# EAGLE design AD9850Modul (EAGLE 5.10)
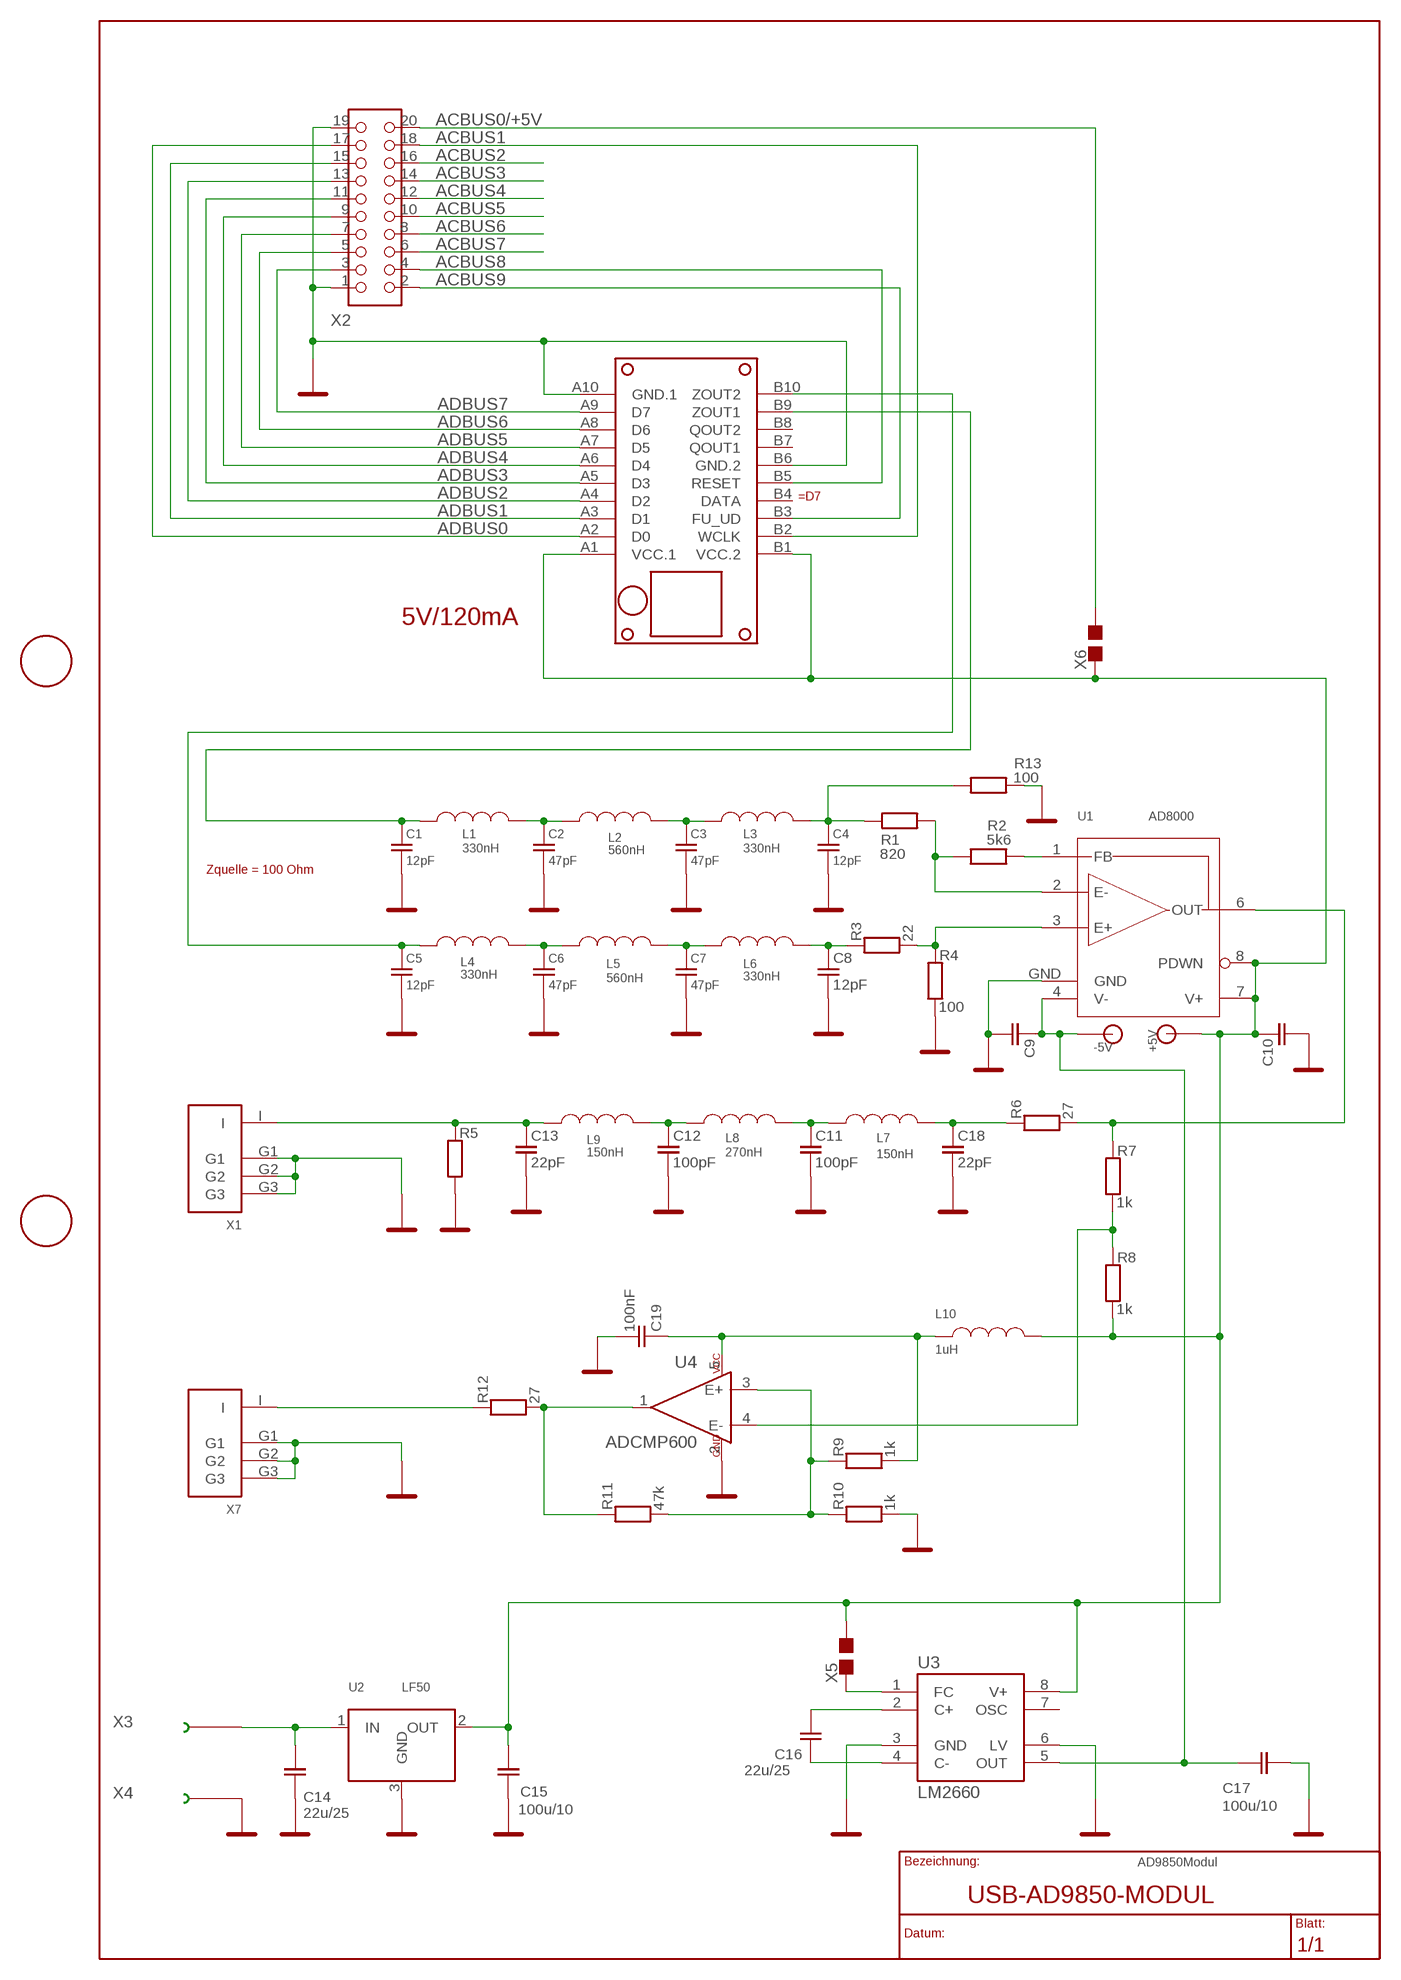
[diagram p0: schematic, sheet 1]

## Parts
C1  12pF  SMD-0603  [SOT-0603]
C2  47pF  SMD-0603  [SOT-0603]
C3  47pF  SMD-0603  [SOT-0603]
C4  12pF  SMD-0603  [SOT-0603]
C5  12pF  SMD-0603  [SOT-0603]
C6  47pF  SMD-0603  [SOT-0603]
C7  47pF  SMD-0603  [SOT-0603]
C8  12pF  SMD-0603  [SOT-0603]
C9  SMD-0603  [SOT-0603]
C10  SMD-0603  [SOT-0603]
C11  100pF  SMD-0603  [SOT-0603]
C12  100pF  SMD-0603  [SOT-0603]
C13  22pF  SMD-0603  [SOT-0603]
C14  22u/25  SMD-1210  [SOT-1210]
C15  100u/10  SMD-1210  [SOT-1210]
C16  22u/25  SMD-1210  [SOT-1210]
C17  100u/10  SMD-1210  [SOT-1210]
C18  22pF  SMD-0603  [SOT-0603]
C19  100nF  SMD-0603  [SOT-0603]
L1  330nH  SMD-1008  [SMD-1008]
L2  560nH  SMD-1008  [SMD-1008]
L3  330nH  SMD-1008  [SMD-1008]
L4  330nH  SMD-1008  [SMD-1008]
L5  560nH  SMD-1008  [SMD-1008]
L6  330nH  SMD-1008  [SMD-1008]
L7  150nH  SMD-1008  [SMD-1008]
L8  270nH  SMD-1008  [SMD-1008]
L9  150nH  SMD-1008  [SMD-1008]
L10  1uH  SMD-1008  [SMD-1008]
M1  CHINA_DDS  [CHINA_DDS]
R1  820  SMD-0603  [SMD-0603]
R2  5k6  SMD-0603  [SMD-0603]
R3  22  SMD-0603  [SMD-0603]
R4  100  SMD-0603  [SMD-0603]
R5  SMD-0603  [SMD-0603]
R6  27  SMD-0603  [SMD-0603]
R7  1k  SMD-0603  [SMD-0603]
R8  1k  SMD-0603  [SMD-0603]
R9  1k  SMD-0603  [SMD-0603]
R10  1k  SMD-0603  [SMD-0603]
R11  47k  SMD-0603  [SMD-0603]
R12  27  SMD-0603  [SMD-0603]
R13  100  SMD-0603  [SMD-0603]
U1  AD8000  [SO-8EXP]
U2  LF50  LF-XXX  [DPAK]
U3  LM2660  [SO-8]
U4  ADCMP600  [SOT23-5]
X1  CINCH-S  [CINCH-S]
X2  BUCHSE2X10/90  [BUCHSE2X10/90]
X3  LÖTÖSEQ  [LÖTÖSEQ]
X4  LÖTÖSEQ  [LÖTÖSEQ]
X5  PATCH  [PATCH]
X6  PATCH  [PATCH]
X7  CINCH-S  [CINCH-S]

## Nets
+5V: C10.2 C15.2 L10.2 M1.A1(VCC.1) M1.B1(VCC.2) R8.1 U1.7(V+) U1.8(PDWN) U2.2(OUT) U3.8(V+) X5.2 X6.1
-5V: C9.2 C17.2 U1.4(V-) U3.5(OUT)
ACBUS0/+5V: X2.20 X6.2
ACBUS1: M1.B2(WCLK) X2.18
ACBUS2: X2.16
ACBUS3: X2.14
ACBUS4: X2.12
ACBUS5: X2.10
ACBUS6: X2.8
ACBUS7: X2.6
ACBUS8: M1.B5(RESET) X2.4
ACBUS9: M1.B3(FU_UD) X2.2
ADBUS0: M1.A2(D0) X2.17
ADBUS1: M1.A3(D1) X2.15
ADBUS2: M1.A4(D2) X2.13
ADBUS3: M1.A5(D3) X2.11
ADBUS4: M1.A6(D4) X2.9
ADBUS5: M1.A7(D5) X2.7
ADBUS6: M1.A8(D6) X2.5
ADBUS7: M1.A9(D7) X2.3
GND: C1.1 C2.1 C3.1 C4.1 C5.1 C6.1 C7.1 C8.1 C9.1 C10.1 C11.1 C12.1 C13.1 C14.1 C15.1 C17.1 C18.1 C19.1 M1.A10(GND.1) M1.B6(GND.2) R4.1 R5.1 R10.1 R13.1 U1.GND U2.3(GND) U3.3(GND) U3.6(LV) U4.2(GND) X1.G1 X1.G2 X1.G3 X2.1 X2.19 X4.1 X7.G1 X7.G2 X7.G3
N$1: R2.1 U1.1(FB)
N$2: R1.1 R2.2 U1.2(E-)
N$3: C1.2 L1.1 M1.B9(ZOUT1)
N$4: C2.2 L1.2 L2.1
N$5: C3.2 L2.2 L3.1
N$6: C4.2 L3.2 R1.2 R13.2
N$7: C5.2 L4.1 M1.B10(ZOUT2)
N$8: C6.2 L4.2 L5.1
N$9: C7.2 L5.2 L6.1
N$10: C8.2 L6.2 R3.2
N$11: R3.1 R4.2 U1.3(E+)
N$12: R6.1 R7.2 U1.6(OUT)
N$13: C11.2 L7.1 L8.2
N$14: C12.2 L8.1 L9.2
N$15: C13.2 L9.1 R5.2 X1.I
N$16: C14.2 U2.1(IN) X3.1
N$17: C16.1 U3.4(C-)
N$18: C16.2 U3.2(C+)
N$19: U3.1(FC) X5.1
N$20: C18.2 L7.2 R6.2
N$21: C19.2 L10.1 R9.1 U4.5(VCC)
N$22: R7.1 R8.2 U4.4(E-)
N$23: R9.2 R10.2 R11.1 U4.3(E+)
N$24: R11.2 R12.1 U4.1(OUT)
N$25: R12.2 X7.I
Unconnected: M1.B4(DATA) M1.B7(QOUT1) M1.B8(QOUT2) U3.7(OSC)

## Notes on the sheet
- =D7
- 5V/120mA
- Zquelle = 100 Ohm
- USB-AD9850-MODUL

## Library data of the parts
C1-C13 C18 C19 = C_KERAM:SMD-0603
C14-C17 = C_KERAM:SMD-1210
L1-L10 = L:SMD-1008
M1 = HAMRAD:CHINA_DDS
R1-R13 = R:SMD-0603
U1 = ANALOG_D:AD8000
U2 = SGS:LF-XXX
U3 = NSC:LM2660
U4 = ANALOG_D:ADCMP600: Komparator 3.5 ns
X1 X7 = HAMRAD:CINCH-S
X2 = PINHD-Q:BUCHSE2X10/90
X3 X4 = Z_CONNEC:LÖTÖSEQ
X5 X6 = Z_CONNEC:PATCH

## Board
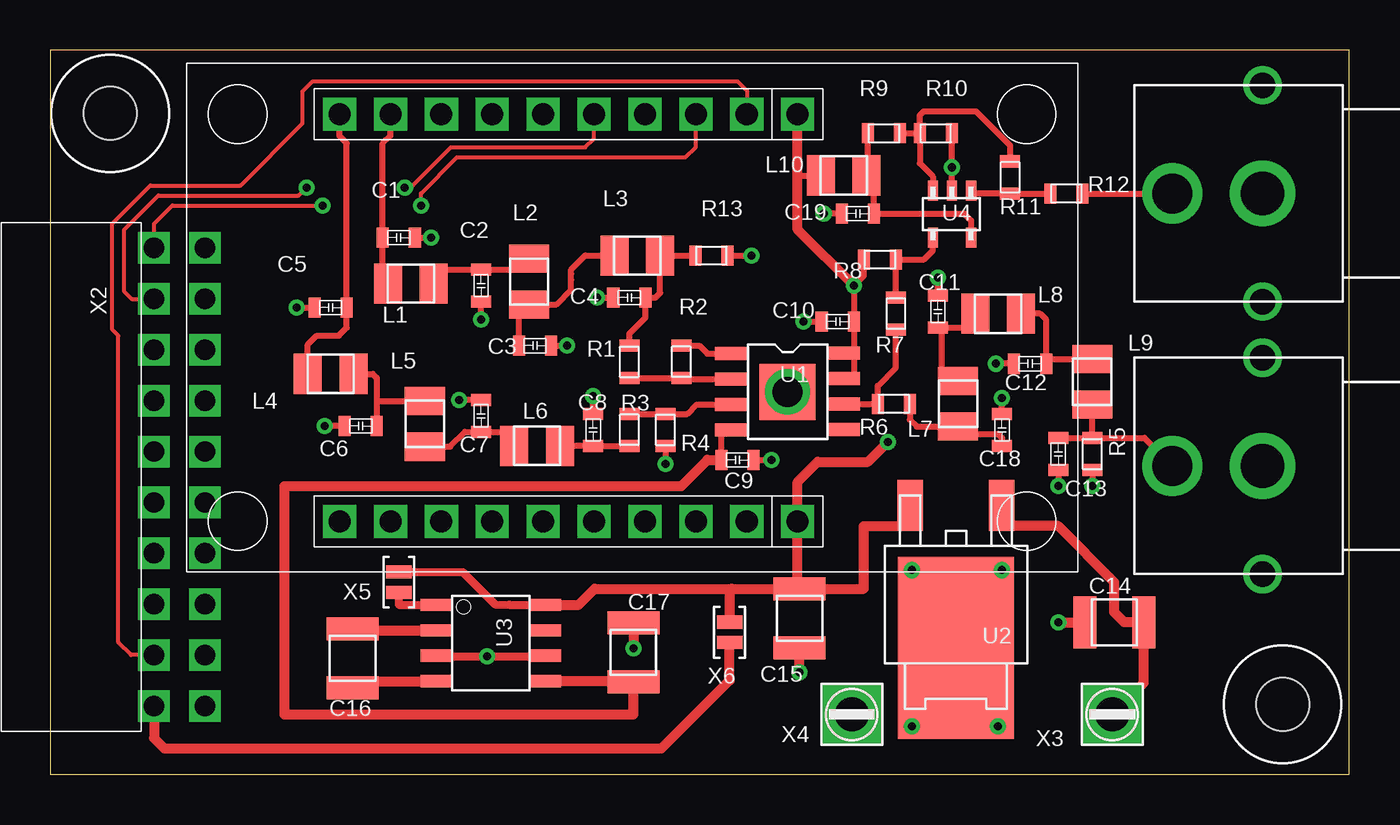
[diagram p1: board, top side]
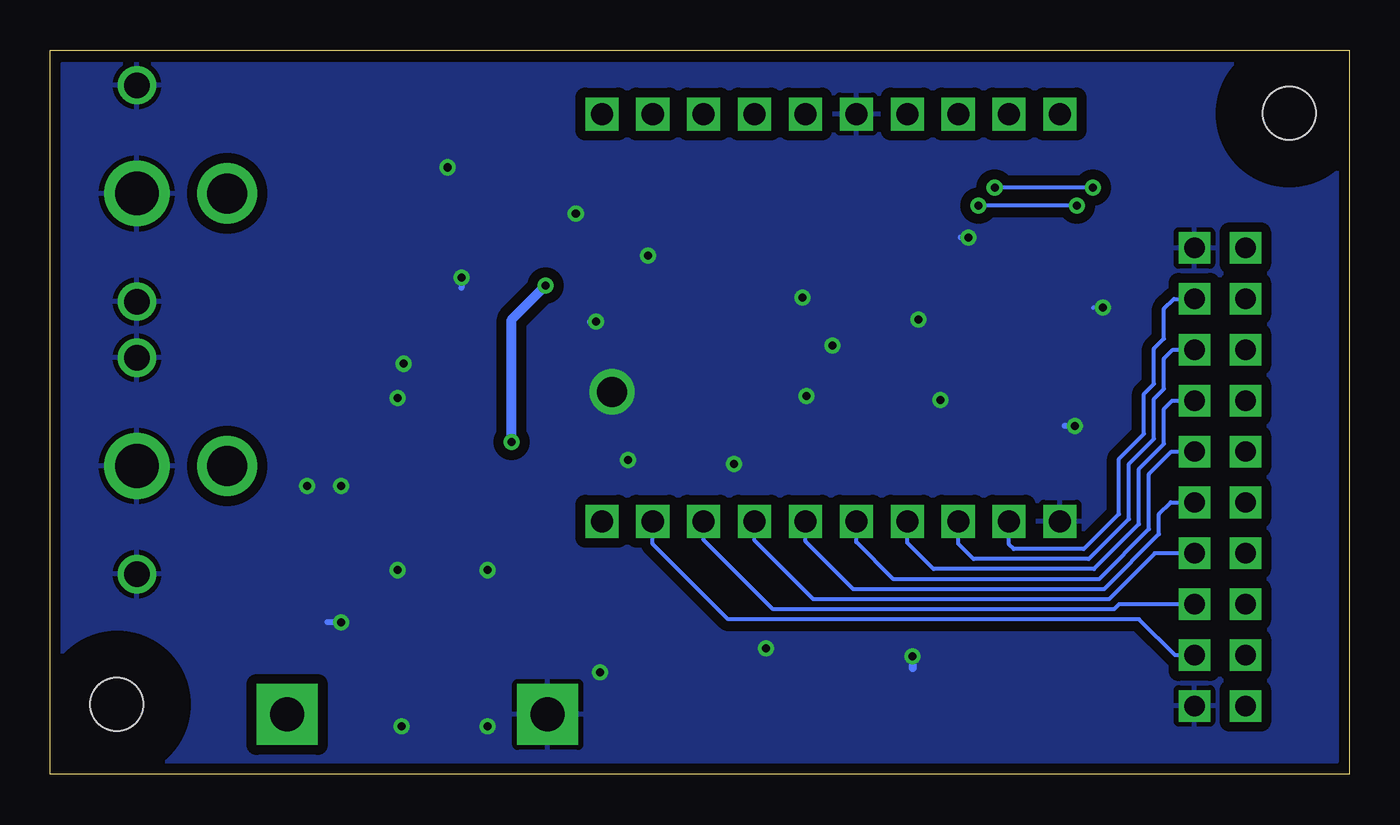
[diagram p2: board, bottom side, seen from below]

Size 64.83 x 36.16 mm. Coordinates in mm from the lower left corner, seen from the top.
Outline: 0,0 64.83,0 64.83,36.16 0,36.16 0,0
Copper layers (1*16): Top 0.035mm / dielectric 1.5mm / Bottom 0.035mm
Design rules "default": minimum track width 0.15mm, minimum drill 0.3mm, track to track 0.15mm, track to pad 0.15mm, pad to pad 0.15mm, via to via 0.15mm, smd to smd 0mil, copper to edge 0.15mm, drill to drill 0.15mm, minimum pad ring 0.15mm, minimum via ring 0.15mm, stop-mask expansion 4mil, vias tented up to drill 0mil, thermal gap 10mil

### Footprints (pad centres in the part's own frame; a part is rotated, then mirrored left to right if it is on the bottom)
SOT-0603 = smd 0.6 x 1: 1 -0.8,0; 2 0.8,0
SOT-1210 = smd 1.143 x 2.591: 1 -1.473,0; 2 1.473,0
SMD-1008 = smd 1.4 x 2: 1 -1.14,0; 2 1.14,0
CHINA_DDS = drill 1.1 square: A1 -10.16,-12.7; A2 -10.16,-10.16; A3 -10.16,-7.62; A4 -10.16,-5.08; A5 -10.16,-2.54; A6 -10.16,0; A7 -10.16,2.54; A8 -10.16,5.08; A9 -10.16,7.62; A10 -10.16,10.16; B1 10.16,-12.7; B2 10.16,-10.16; B3 10.16,-7.62; B4 10.16,-5.08; B5 10.16,-2.54; B6 10.16,0; B7 10.16,2.54; B8 10.16,5.08; B9 10.16,7.62; B10 10.16,10.16
SMD-0603 = smd 0.6 x 1: 1 -0.8,0; 2 0.8,0
SO-8EXP = smd 0.66 x 1.6: 1 -1.905,-2.819; 2 -0.635,-2.819; 3 0.635,-2.819; 4 1.905,-2.819; 5 1.88,2.819; 6 0.61,2.819; 7 -0.66,2.819; 8 -1.93,2.819 | smd 2.794 x 2.794: GND 0,0
DPAK = smd 1.27 x 2.54: 1 -2.286,-2.032; 2 2.286,-2.032 | smd 5.8 x 9.1: 3 0,5.08
SO-8 = smd 0.61 x 1.524: 1 -1.27,-2.743; 2 0,-2.743; 3 1.27,-2.743; 4 2.54,-2.743; 5 2.54,2.743; 6 1.27,2.743; 7 0,2.743; 8 -1.27,2.743
SOT23-5 = smd 0.508 x 1.016: 1 -0.953,-1.143; 2 0,-1.143; 3 0.953,-1.143; 4 0.953,1.206; 5 -0.953,1.206
DRIL-2,5 = hole 2.642: 0,0
CINCH-S = drill 2.184 pad 2.8 round: G1 0,0 | drill 1.27 pad 1.778 round: G2 0,5.4; G3 0,-5.4 | drill 2 pad 2.54 round: I 4.5,0
BUCHSE2X10/90 = drill 1.016 pad 1.575 square: 1 -11.43,-1.27; 2 -11.43,-3.81; 3 -8.89,-1.27; 4 -8.89,-3.81; 5 -6.35,-1.27; 6 -6.35,-3.81; 7 -3.81,-1.27; 8 -3.81,-3.81; 9 -1.27,-1.27; 10 -1.27,-3.81; 11 1.27,-1.27; 12 1.27,-3.81; 13 3.81,-1.27; 14 3.81,-3.81; 15 6.35,-1.27; 16 6.35,-3.81; 17 8.89,-1.27; 18 8.89,-3.81; 19 11.43,-1.27; 20 11.43,-3.81
LÖTÖSEQ = drill 1.702 pad 3.048 square: 1 0,0
PATCH = smd 0.66 x 1.27: 1 -0.508,0; 2 0.508,0

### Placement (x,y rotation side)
C1  17.4,26.8 180 top
C2  21.5,24.4 90 top
C3  24.2,21.4 180 top
C4  28.9,23.8 0 top
C5  14,23.3 0 top
C6  15.5,17.4 0 top
C7  21.5,17.9 270 top
C8  27.1,17.2 270 top
C9  34.3,15.7 180 top
C10  39.3,22.6 0 top
C11  44.3,23.1 270 top
C12  48.9,20.5 0 top
C13  50.3,16 90 top
C14  53.1,7.6 0 top
C15  37.4,7.8 90 top
C16  15.1,5.8 90 top
C17  29.1,6.1 270 top
C18  47.5,17.2 270 top
C19  40.3,28 0 top
L1  18,24.5 0 top
L2  23.9,24.6 270 top
L3  29.3,25.9 0 top
L4  14,20 0 top
L5  18.7,17.5 270 top
L6  24.3,16.4 0 top
L7  45.3,18.5 270 top
L8  47.3,23 180 top
L9  52,19.6 90 top
L10  39.6,29.9 180 top
M1  24.6,22.8 90 top
R1  28.9,20.6 90 top
R2  31.5,20.6 270 top
R3  28.9,17.2 270 top
R4  30.7,17.2 90 top
R5  52,16 90 top
R6  42.1,18.5 0 top
R7  42.2,23 270 top
R8  41.4,25.7 0 top
R9  41.6,32 0 top
R10  44.2,32 180 top
R11  47.9,29.8 270 top
R12  50.7,29 0 top
R13  33,25.9 180 top
U1  36.8,19.1 270 top
U2  45.2,11.4 180 top
U3  22,7.2 270 top
U4  45,28 180 top
U$34  [DRIL-2,5]  3,33 0 top
U$35  [DRIL-2,5]  61.5,3.5 0 top
X1  60.5,15.4 180 top
X2  9,14.85 270 top
X3  53,3 90 top
X4  40,3 90 top
X5  17.4,9.6 90 top
X6  33.9,7.1 270 top
X7  60.5,29 180 top

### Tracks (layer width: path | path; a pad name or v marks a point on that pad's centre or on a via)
+5V  (via drill 0.4 pad 0.8)
  Top 0.3: U1.7 40.1,19.76 40.1,21.03 | 40.1,21.03 U1.8 | 40.1,21.03 C10.2 v40.1,24.4 40.6,24.9 R8.1 | C15.2 37.3,9.27 | 37.3,29.9 L10.2
  Top 0.4: U3.8 22.91,8.47 22.2,8.5 20.59,10.11 X5.2
  Top 0.5: v41.8,16.6 40.8,15.6 38.3,15.6 37.3,14.6 M1.A1 37.3,9.27 | M1.B1 37.3,29.9 37.3,27.2 v40.1,24.4 | U2.2 42.91,12.4 40.6,12.4 40.6,9.27 C15.2 34,9.27 | U3.8 26.37,8.47 27.17,9.27 34,9.27 | X6.1 33.9,9.17 34,9.27
  Bottom 0.5: v41.8,16.6 41.8,22.7 v40.1,24.4
-5V
  Top 0.3: U1.4 33.5,17.2 C9.2
  Top 0.4: C17.2 29.1,4.66
  Top 0.5: C9.2 32.8,15.7 31.5,14.4 11.7,14.4 11.7,3 29.1,3 C17.2 | 29.1,4.66 U3.5
ACBUS0/+5V
  Top 0.5: X2.20 5.19,1.81 5.7,1.3 30.5,1.3 33.9,4.7 X6.2
ACBUS1
  Top 0.2: X2.18 4.04,5.96 3.4,6.6 3.4,21.9 3.1,22.2 3.1,27.5 5,29.4 9.5,29.4 12.6,32.5 12.6,34.1 13.1,34.6 34.3,34.6 34.76,34.14 M1.B2
ACBUS8  (via drill 0.4 pad 0.8)
  Top 0.2: X2.4 4.06,23.74 3.7,24.1 3.7,27.2 5.4,28.9 12.4,28.9 v12.8,29.3 | M1.B5 27.14,31.74 26.7,31.3 20,31.3 18,29.3 v17.7,29.3
  Bottom 0.2: v12.8,29.3 v17.7,29.3
ACBUS9  (via drill 0.4 pad 0.8)
  Top 0.2: X2.2 5.19,27.49 6.1,28.4 v13.6,28.4 | M1.B3 32.22,31.32 31.7,30.8 20.3,30.8 18.5,29 v18.5,28.4
  Bottom 0.2: v13.6,28.4 v18.5,28.4
ADBUS0
  Bottom 0.2: M1.A2 34.76,11.51 31,7.75 10.5,7.75 8.71,5.96 X2.17
ADBUS1
  Bottom 0.2: M1.A3 32.22,11.72 28.75,8.25 11.75,8.25 11.5,8.5 X2.15
ADBUS2
  Bottom 0.2: M1.A4 29.68,11.68 26.75,8.75 12,8.75 9.71,11.04 X2.13
ADBUS3
  Bottom 0.2: M1.A5 27.14,11.64 24.75,9.25 12.25,9.25 9.5,12 9.5,13 8.92,13.58 X2.11
ADBUS4
  Bottom 0.2: M1.A6 24.6,11.6 22.75,9.75 12.5,9.75 10,12.25 10,15 8.88,16.12 X2.9
ADBUS5
  Bottom 0.2: M1.A7 22.06,11.56 20.75,10.25 12.75,10.25 10.5,12.5 10.5,15.25 9.25,16.5 9.25,18.25 8.84,18.66 X2.7
ADBUS6
  Bottom 0.2: M1.A8 19.52,11.52 18.75,10.75 13,10.75 11,12.75 11,15.5 9.75,16.75 9.75,18.75 9.25,19.25 9.25,20.75 8.8,21.2 X2.5
ADBUS7
  Bottom 0.2: M1.A9 16.98,11.48 16.75,11.25 13.25,11.25 11.5,13 11.5,15.75 10.25,17 10.25,19 9.75,19.5 9.75,21.25 9.25,21.75 9.25,23.25 8.76,23.74 X2.3
GND  (via drill 0.4 pad 0.8, 1.5 pad 0.8)
  Top 0.3: v12.3,23.3 C5.1 | C1.1 v19,26.8 | C6.1 v13.7,17.4 | v21.5,22.7 C2.1 | C3.1 v25.8,21.4 | C8.1 v27.1,18.9 | C7.1 v20.4,18.7 | R4.1 v30.7,15.5 | C9.1 v36,15.7 | v37.6,22.6 C10.1 | U2.3 45.2,4.5 v47.3,2.4 | v27.3,23.8 C4.1 | R5.1 v52,14.4 | C13.1 v50.3,14.4 | C12.1 v47.2,20.5 | C11.1 v44.3,24.8 | C18.1 v47.5,18.8 | C19.1 v38.6,28 | U4.2 v45,30.3 R10.1 | R13.1 v35,25.9
  Top 0.4: U3.3 19.29,5.9 v21.8,5.9 24.71,5.9 U3.6 | C17.1 29.1,7.6
  Top 0.5: v37.4,5.1 C15.1 | v50.3,7.6 C14.1 | 29.1,7.6 v29.1,6.3
  Bottom 0.2: v12.3,23.3 12.8,23.3
  Bottom 0.3: v19,26.8 19.4,26.8 | v13.7,17.4 14.2,17.4 | v21.5,22.7 21.5,22.5 | v25.8,21.4 25.7,21.4 | v27.1,18.9 27.1,18.7 | v20.4,18.7 20.6,18.7 | v30.7,15.5 30.7,15.6 30.6,15.7 | v36,15.7 35.8,15.7 | v37.6,22.6 37.9,22.6 | v37.4,5.1 37.4,5.3 | v50.3,7.6 51,7.6 | v27.3,23.8 27.4,23.8 | v52,14.4 52,14.5 | v50.3,14.4 50.3,14.5 | v47.2,20.5 47.4,20.5 | v44.3,24.8 44.3,24.3 | v47.5,18.8 47.5,18.6 | v38.6,28 38.8,28 | v45,30.3 45,30.2 | v35,25.9 34.9,25.9
  Bottom 0.4: v21.8,5.9 21.8,5.3
  other vias: 36.8,19.1 47.5,10.2 43,10.2 43,2.4
  pour Bottom (isolate 0.5): 0.64,0.64 64.22,0.64 64.22,35.47 0.64,35.47
N$1
  Top 0.3: U1.1 32.8,21 32.4,21.4 R2.1
N$2
  Top 0.3: R1.1 R2.2 31.57,19.73 U1.2
N$3
  Top 0.3: M1.B9 16.98,31.88 16.6,31.5 C1.2 16.6,24.5 L1.1
N$4
  Top 0.3: L1.2 19.14,25.2 C2.2 23.9,25.2 L2.1
N$5
  Top 0.3: L3.1 26.7,25.9 26,25.2 26,25 26,24.7 26,24.2 25.26,23.46 L2.2 23.4,22.96 C3.2
N$6
  Top 0.3: R1.2 28.9,22 29.7,22.8 C4.2 30.2,23.8 30.44,24.04 L3.2 R13.2
N$7
  Top 0.3: M1.B10 14.44,31.86 14.8,31.5 C5.2 14.8,22.3 14.4,21.9 13.3,21.9 12.86,21.46 L4.1
N$8
  Top 0.3: L4.2 16.1,20 16.3,19.8 16.3,18.6 | 16.3,18.6 C6.2 | L5.1 16.34,18.64 16.3,18.6
N$9
  Top 0.3: L5.2 19.96,16.36 20.7,17.1 C7.2 23.16,17.1 L6.1
N$10
  Top 0.3: R3.2 C8.2 L6.2
N$11
  Top 0.3: R3.1 R4.2 31.8,18 32.27,18.46 U1.3
N$12
  Top 0.3: U1.6 R6.1 41.3,19.4 42.2,20.3 R7.2
N$13
  Top 0.3: L7.1 44.5,19.64 44.5,22.3 C11.2 46.16,22.3 L8.2
N$14
  Top 0.3: L8.1 49.4,23 49.7,22.7 C12.2 49.94,20.74 L9.2
N$15
  Top 0.3: X1.I 54.6,16.8 R5.2 | C13.2 R5.2 | R5.2 L9.1
N$16
  Top 0.5: U2.1 47.49,12.4 50.3,12.4 53.1,9.6 53.1,8.1 53.6,7.6 C14.2 54.57,4.57 X3.1
N$17
  Top 0.5: U3.4 15.1,4.66 C16.1
N$18
  Top 0.4: C16.2 15.1,7.2
  Top 0.5: 15.1,7.2 U3.2
N$19
  Top 0.4: U3.1 17.39,8.47 X5.1
N$20
  Top 0.3: R6.2 42.9,17.7 43.24,17.36 L7.2 45.66,17 47.3,17 47.5,16.8 C18.2
N$21
  Top 0.3: U4.5 45.95,27.65 45.6,28 C19.2 41.1,29.54 arc90 L10.1 40.8,29.96 R9.1
N$22
  Top 0.3: R7.1 R8.2 43.6,25.7 44.05,26.15 U4.4
N$23
  Top 0.3: U4.3 44.05,29.85 43.4,30.5 R10.2 | R9.2 R10.2 | R11.1 47.9,31.4 46.2,33.1 43.6,33.1 43.4,32.9 R10.2
N$24
  Top 0.3: R12.1 R11.2 45.95,29 U4.1
N$25
  Top 0.3: R12.2 X7.I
